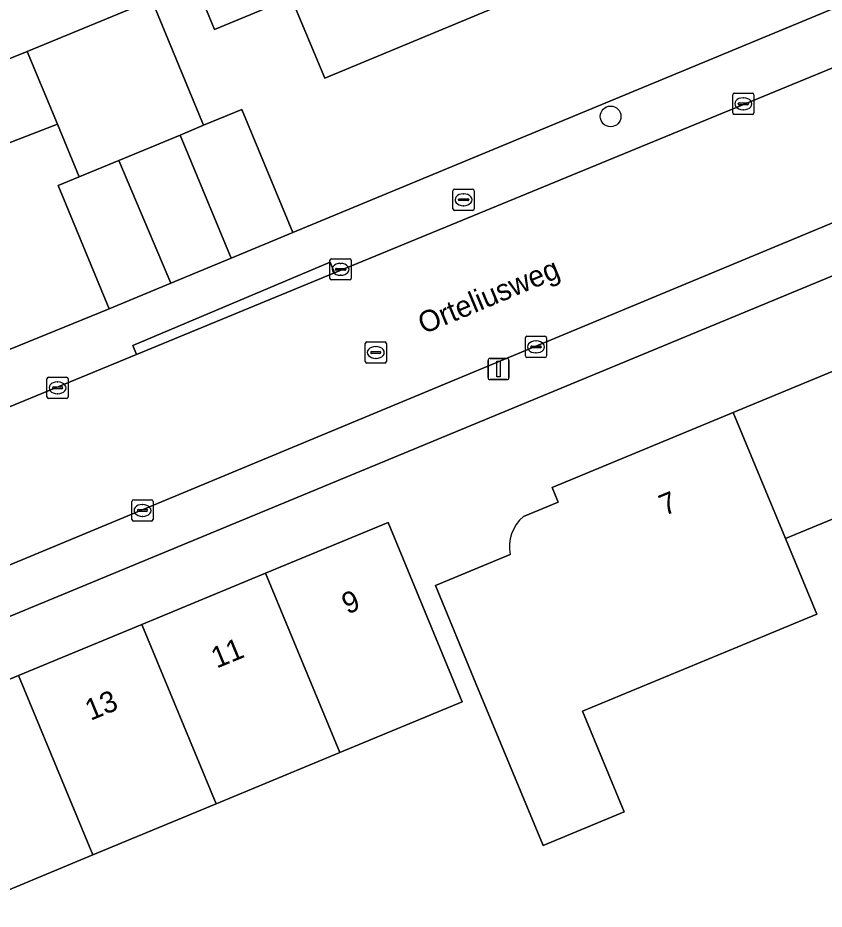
# Model space of a CAD drawing. Extents: x 162989 to 165008, y 383432 to 384338.
# Drawn here: x 163906.47 to 163944.51, y 383891.46 to 383933.52 of the extents above; entities that cross this region are included whole.
import ezdxf

# ---------------------------------------------------------------- set-up
doc = ezdxf.new("R2010")
doc.units = 0
for name, color, linetype in [('IMGEO_Boom', 7, 'Continuous'), ('IMGEO_Brandkraan', 7, 'Continuous'), ('IMGEO_Erf', 7, 'Continuous'), ('IMGEO_Kolk', 7, 'Continuous'), ('IMGEO_Lichtmast', 7, 'Continuous'), ('IMGEO_Openbare_ruimte_label', 7, 'Continuous'), ('IMGEO_Pand', 7, 'Continuous'), ('IMGEO_Pand_nummerreeks', 7, 'Continuous'), ('IMGEO_Rijbaan_lokaal_open', 7, 'Continuous'), ('IMGEO_Rioolput', 7, 'Continuous'), ('IMGEO_Voetpad_open', 7, 'Continuous')]:
    doc.layers.add(name, color=color, linetype=linetype)

msp = doc.modelspace()

# ---------------------------------------------------------------- linework, layer by layer
at = {"layer": 'IMGEO_Boom'}
msp.add_circle((163934.436, 383928.867), 0.489, dxfattribs=at)
at = {"layer": 'IMGEO_Brandkraan'}
for p, q in [((163926.998, 383924.509), (163926.998, 383925.361)), ((163927.073, 383925.435), (163927.925, 383925.435)), ((163927.999, 383925.361), (163927.999, 383924.509)), ((163927.257, 383924.929), (163927.257, 383924.941)), ((163927.695, 383924.892), (163927.297, 383924.892)), ((163927.3, 383924.978), (163927.698, 383924.978)), ((163927.486, 383925.215), (163927.511, 383925.215)), ((163927.741, 383924.941), (163927.741, 383924.929)), ((163927.925, 383924.435), (163927.073, 383924.435)), ((163927.509, 383924.655), (163927.484, 383924.655))]:
    msp.add_line(p, q, dxfattribs=at)
for points in [[(163926.998, 383924.509), (163926.998, 383925.361)], [(163927.073, 383925.435), (163927.925, 383925.435)], [(163927.999, 383925.361), (163927.999, 383924.509)], [(163927.925, 383924.435), (163927.073, 383924.435)]]:
    msp.add_lwpolyline(points, dxfattribs=at)
for centre, radius, start, end in [((163927.075, 383925.359), 0.0765, 91.552, 178.448), ((163927.075, 383925.359), 0.0765, 91.552, 178.448), ((163927.923, 383925.359), 0.0765, 1.552, 88.448), ((163927.923, 383925.359), 0.0765, 1.552, 88.448), ((163927.297, 383924.938), 0.0403, 85.8775, 175.7526), ((163927.294, 383924.928), 0.0366, 178.938, 274.7102), ((163927.698, 383924.935), 0.043, 264.8664, 352.4533), ((163927.702, 383924.94), 0.0386, 1.7309, 96.639), ((163927.075, 383924.511), 0.0765, 181.552, 268.448), ((163927.075, 383924.511), 0.0765, 181.552, 268.448), ((163927.923, 383924.511), 0.0765, 271.552, 358.448), ((163927.923, 383924.511), 0.0765, 271.552, 358.448)]:
    msp.add_arc(centre, radius, start, end, dxfattribs=at)
for centre, major_axis, ratio, start_param, end_param in [((163927.485, 383924.935), (-0.387, 0.002), 0.722429, 4.712389, 7.853982), ((163927.51, 383924.935), (-0.39, 0.002), 0.717154, 1.570796, 4.712389)]:
    msp.add_ellipse(centre, major_axis=major_axis, ratio=ratio, start_param=start_param, end_param=end_param, dxfattribs=at)
at = {"layer": 'IMGEO_Erf'}
for points in [[(163946.821, 383941.418), (163938.242, 383937.855), (163929.662, 383934.293), (163920.948, 383930.674), (163919.371, 383934.472), (163915.75, 383932.969), (163914.83, 383935.186), (163918.45, 383936.689), (163927.165, 383940.307), (163929.854, 383941.424), (163928.821, 383943.984), (163931.569, 383945.125), (163931.805, 383944.556), (163934.921, 383945.85), (163934.549, 383946.958), (163943.055, 383950.486), (163944.361, 383947.342), (163949.293, 383949.389)], [(163903.673, 383930.627), (163906.917, 383931.923), (163912.786, 383934.359), (163915.238, 383928.452), (163917.039, 383929.2), (163919.451, 383923.393), (163973.469, 383945.794)], [(163964.512, 383929.456), (163893.635, 383900.12), (163894.721, 383897.605), (163900.679, 383900.072), (163906.5, 383902.482), (163912.322, 383904.893), (163918.161, 383907.311), (163923.936, 383909.702), (163927.44, 383901.238), (163921.666, 383898.847), (163915.826, 383896.429), (163910.005, 383894.018), (163904.184, 383891.608), (163898.226, 383889.141)], [(163900.656, 383915.672), (163910.782, 383919.794), (163908.371, 383925.6), (163909.37, 383926.015), (163908.336, 383928.506), (163904.998, 383927.211)], [(163930.32, 383909.987), (163931.964, 383910.668), (163931.677, 383911.36), (163940.224, 383914.899), (163948.809, 383918.454)], [(163948.089, 383911.18), (163942.69, 383908.945), (163944.168, 383905.374), (163941.778, 383904.385), (163933.11, 383900.797), (163935.075, 383896.047), (163931.249, 383894.463), (163928.082, 383902.114), (163926.17, 383906.733), (163929.7, 383908.194)]]:
    msp.add_lwpolyline(points, dxfattribs=at)
msp.add_arc((163931.55, 383908.558), 1.885, 130.7192, 191.1311, dxfattribs=at)
at = {"layer": 'IMGEO_Kolk'}
for p, q in [((163940.198, 383929.037), (163940.198, 383929.889)), ((163940.273, 383929.963), (163941.125, 383929.963)), ((163941.199, 383929.889), (163941.199, 383929.037)), ((163940.457, 383929.457), (163940.457, 383929.469)), ((163940.5, 383929.506), (163940.898, 383929.506)), ((163940.686, 383929.743), (163940.711, 383929.743)), ((163940.941, 383929.469), (163940.941, 383929.457)), ((163940.895, 383929.42), (163940.497, 383929.42)), ((163940.709, 383929.183), (163940.684, 383929.183)), ((163941.125, 383928.963), (163940.273, 383928.963)), ((163921.196, 383921.225), (163921.196, 383922.077)), ((163921.271, 383922.151), (163922.123, 383922.151)), ((163921.684, 383921.931), (163921.709, 383921.931)), ((163922.197, 383922.077), (163922.197, 383921.225)), ((163921.455, 383921.645), (163921.455, 383921.657)), ((163921.893, 383921.608), (163921.495, 383921.608)), ((163921.498, 383921.694), (163921.896, 383921.694)), ((163921.939, 383921.657), (163921.939, 383921.645)), ((163922.123, 383921.151), (163921.271, 383921.151)), ((163921.707, 383921.371), (163921.682, 383921.371)), ((163930.414, 383917.564), (163930.414, 383918.416)), ((163930.489, 383918.49), (163931.341, 383918.49)), ((163930.902, 383918.27), (163930.927, 383918.27)), ((163931.415, 383918.416), (163931.415, 383917.564)), ((163930.673, 383917.984), (163930.673, 383917.996)), ((163931.111, 383917.947), (163930.713, 383917.947)), ((163930.716, 383918.033), (163931.114, 383918.033)), ((163930.925, 383917.71), (163930.9, 383917.71)), ((163931.157, 383917.996), (163931.157, 383917.984)), ((163931.341, 383917.49), (163930.489, 383917.49)), ((163907.846, 383915.633), (163907.846, 383916.485)), ((163907.921, 383916.559), (163908.773, 383916.559)), ((163908.847, 383916.485), (163908.847, 383915.633)), ((163908.105, 383916.053), (163908.105, 383916.065)), ((163908.543, 383916.016), (163908.145, 383916.016)), ((163908.148, 383916.102), (163908.546, 383916.102)), ((163908.334, 383916.339), (163908.359, 383916.339)), ((163908.589, 383916.065), (163908.589, 383916.053)), ((163908.357, 383915.779), (163908.332, 383915.779)), ((163908.773, 383915.559), (163907.921, 383915.559)), ((163911.852, 383909.847), (163911.852, 383910.699)), ((163911.927, 383910.773), (163912.779, 383910.773)), ((163912.34, 383910.553), (163912.365, 383910.553)), ((163912.853, 383910.699), (163912.853, 383909.847)), ((163912.111, 383910.267), (163912.111, 383910.279)), ((163912.549, 383910.23), (163912.151, 383910.23)), ((163912.154, 383910.316), (163912.552, 383910.316)), ((163912.595, 383910.279), (163912.595, 383910.267)), ((163912.779, 383909.773), (163911.927, 383909.773)), ((163912.363, 383909.993), (163912.338, 383909.993))]:
    msp.add_line(p, q, dxfattribs=at)
for points in [[(163940.198, 383929.037), (163940.198, 383929.889)], [(163940.273, 383929.963), (163941.125, 383929.963)], [(163941.199, 383929.889), (163941.199, 383929.037)], [(163941.125, 383928.963), (163940.273, 383928.963)], [(163921.196, 383921.225), (163921.196, 383922.077)], [(163921.271, 383922.151), (163922.123, 383922.151)], [(163922.197, 383922.077), (163922.197, 383921.225)], [(163922.123, 383921.151), (163921.271, 383921.151)], [(163930.414, 383917.564), (163930.414, 383918.416)], [(163930.489, 383918.49), (163931.341, 383918.49)], [(163931.415, 383918.416), (163931.415, 383917.564)], [(163931.341, 383917.49), (163930.489, 383917.49)], [(163907.846, 383915.633), (163907.846, 383916.485)], [(163907.921, 383916.559), (163908.773, 383916.559)], [(163908.847, 383916.485), (163908.847, 383915.633)], [(163908.773, 383915.559), (163907.921, 383915.559)], [(163911.852, 383909.847), (163911.852, 383910.699)], [(163911.927, 383910.773), (163912.779, 383910.773)], [(163912.853, 383910.699), (163912.853, 383909.847)], [(163912.779, 383909.773), (163911.927, 383909.773)]]:
    msp.add_lwpolyline(points, dxfattribs=at)
for centre, radius, start, end in [((163940.275, 383929.887), 0.0765, 91.552, 178.448), ((163940.275, 383929.887), 0.0765, 91.552, 178.448), ((163941.123, 383929.887), 0.0765, 1.552, 88.448), ((163941.123, 383929.887), 0.0765, 1.552, 88.448), ((163940.497, 383929.466), 0.0403, 85.8775, 175.7526), ((163940.494, 383929.456), 0.0366, 178.938, 274.7102), ((163940.898, 383929.463), 0.043, 264.8664, 352.4533), ((163940.902, 383929.468), 0.0386, 1.7309, 96.639), ((163940.275, 383929.039), 0.0765, 181.552, 268.448), ((163940.275, 383929.039), 0.0765, 181.552, 268.448), ((163941.123, 383929.039), 0.0765, 271.552, 358.448), ((163941.123, 383929.039), 0.0765, 271.552, 358.448), ((163921.273, 383922.075), 0.0765, 91.552, 178.448), ((163921.273, 383922.075), 0.0765, 91.552, 178.448), ((163922.121, 383922.075), 0.0765, 1.552, 88.448), ((163922.121, 383922.075), 0.0765, 1.552, 88.448), ((163921.495, 383921.654), 0.0403, 85.8775, 175.7526), ((163921.492, 383921.644), 0.0366, 178.938, 274.7102), ((163921.896, 383921.651), 0.043, 264.8664, 352.4533), ((163921.9, 383921.656), 0.0386, 1.7309, 96.639), ((163921.273, 383921.227), 0.0765, 181.552, 268.448), ((163921.273, 383921.227), 0.0765, 181.552, 268.448), ((163922.121, 383921.227), 0.0765, 271.552, 358.448), ((163922.121, 383921.227), 0.0765, 271.552, 358.448), ((163930.491, 383918.414), 0.0765, 91.552, 178.448), ((163930.491, 383918.414), 0.0765, 91.552, 178.448), ((163931.339, 383918.414), 0.0765, 1.552, 88.448), ((163931.339, 383918.414), 0.0765, 1.552, 88.448), ((163930.713, 383917.993), 0.0403, 85.8775, 175.7526), ((163930.71, 383917.983), 0.0366, 178.938, 274.7102), ((163931.114, 383917.99), 0.043, 264.8664, 352.4533), ((163931.118, 383917.995), 0.0386, 1.7309, 96.639), ((163930.491, 383917.566), 0.0765, 181.552, 268.448), ((163930.491, 383917.566), 0.0765, 181.552, 268.448), ((163931.339, 383917.566), 0.0765, 271.552, 358.448), ((163931.339, 383917.566), 0.0765, 271.552, 358.448), ((163907.923, 383916.483), 0.0765, 91.552, 178.448), ((163907.923, 383916.483), 0.0765, 91.552, 178.448), ((163908.771, 383916.483), 0.0765, 1.552, 88.448), ((163908.771, 383916.483), 0.0765, 1.552, 88.448), ((163908.145, 383916.062), 0.0403, 85.8775, 175.7526), ((163908.142, 383916.052), 0.0366, 178.938, 274.7102), ((163908.546, 383916.059), 0.043, 264.8664, 352.4533), ((163908.55, 383916.064), 0.0386, 1.7309, 96.639), ((163907.923, 383915.635), 0.0765, 181.552, 268.448), ((163907.923, 383915.635), 0.0765, 181.552, 268.448), ((163908.771, 383915.635), 0.0765, 271.552, 358.448), ((163908.771, 383915.635), 0.0765, 271.552, 358.448), ((163911.929, 383910.697), 0.0765, 91.552, 178.448), ((163911.929, 383910.697), 0.0765, 91.552, 178.448), ((163912.777, 383910.697), 0.0765, 1.552, 88.448), ((163912.777, 383910.697), 0.0765, 1.552, 88.448), ((163912.151, 383910.276), 0.0403, 85.8775, 175.7526), ((163912.148, 383910.266), 0.0366, 178.938, 274.7102), ((163912.552, 383910.273), 0.043, 264.8664, 352.4533), ((163912.556, 383910.278), 0.0386, 1.7309, 96.639), ((163911.929, 383909.849), 0.0765, 181.552, 268.448), ((163911.929, 383909.849), 0.0765, 181.552, 268.448), ((163912.777, 383909.849), 0.0765, 271.552, 358.448), ((163912.777, 383909.849), 0.0765, 271.552, 358.448)]:
    msp.add_arc(centre, radius, start, end, dxfattribs=at)
for centre, major_axis, ratio, start_param, end_param in [((163940.685, 383929.463), (-0.387, 0.002), 0.722429, 4.712389, 7.853982), ((163940.71, 383929.463), (-0.39, 0.002), 0.717154, 1.570796, 4.712389), ((163921.683, 383921.651), (-0.387, 0.002), 0.722429, 4.712389, 7.853982), ((163921.708, 383921.651), (-0.39, 0.002), 0.717154, 1.570796, 4.712389), ((163930.901, 383917.99), (-0.387, 0.002), 0.722429, 4.712389, 7.853982), ((163930.926, 383917.99), (-0.39, 0.002), 0.717154, 1.570796, 4.712389), ((163908.333, 383916.059), (-0.387, 0.002), 0.722429, 4.712389, 7.853982), ((163908.358, 383916.059), (-0.39, 0.002), 0.717154, 1.570796, 4.712389), ((163912.339, 383910.273), (-0.387, 0.002), 0.722429, 4.712389, 7.853982), ((163912.364, 383910.273), (-0.39, 0.002), 0.717154, 1.570796, 4.712389)]:
    msp.add_ellipse(centre, major_axis=major_axis, ratio=ratio, start_param=start_param, end_param=end_param, dxfattribs=at)
at = {"layer": 'IMGEO_Lichtmast'}
for p, q in [((163928.653, 383916.546), (163928.653, 383917.346)), ((163928.653, 383917.346), (163928.653, 383916.546)), ((163928.753, 383917.446), (163929.543, 383917.446)), ((163929.543, 383917.446), (163928.753, 383917.446)), ((163929.643, 383917.346), (163929.643, 383916.546)), ((163929.643, 383916.546), (163929.643, 383917.346)), ((163929.543, 383916.446), (163928.753, 383916.446)), ((163928.753, 383916.446), (163929.543, 383916.446))]:
    msp.add_line(p, q, dxfattribs=at)
msp.add_lwpolyline([(163929.073, 383917.321), (163929.223, 383917.321), (163929.223, 383916.571), (163929.073, 383916.571), (163929.073, 383917.321)], dxfattribs=at)
for centre, start, end in [((163928.753, 383917.346), 90, 180), ((163928.753, 383917.346), 90, 180), ((163929.543, 383917.346), 0, 90), ((163929.543, 383917.346), 360, 90), ((163928.753, 383916.546), 180, 270), ((163928.753, 383916.546), 180, 270), ((163929.543, 383916.546), 270, 0), ((163929.543, 383916.546), 270, 0)]:
    msp.add_arc(centre, 0.1, start, end, dxfattribs=at)
at = {"layer": 'IMGEO_Pand'}
for points in [[(163927.165, 383940.307), (163918.45, 383936.689), (163914.83, 383935.186), (163915.75, 383932.969), (163919.371, 383934.472), (163920.948, 383930.674), (163929.662, 383934.293)], [(163906.917, 383931.923), (163908.336, 383928.506), (163909.37, 383926.015), (163911.233, 383926.789), (163914.124, 383927.989), (163915.238, 383928.452), (163912.786, 383934.359)], [(163906.917, 383931.923), (163903.673, 383930.627), (163904.998, 383927.211), (163908.336, 383928.506)], [(163917.039, 383929.2), (163915.238, 383928.452), (163914.124, 383927.989), (163916.535, 383922.182), (163919.451, 383923.393)], [(163913.691, 383921.002), (163916.535, 383922.182), (163914.124, 383927.989), (163911.233, 383926.789)], [(163911.233, 383926.789), (163909.37, 383926.015), (163908.371, 383925.6), (163910.782, 383919.794), (163913.691, 383921.002)], [(163948.809, 383918.454), (163940.224, 383914.899), (163942.69, 383908.945), (163948.089, 383911.18), (163949.202, 383908.493), (163952.378, 383909.835), (163951.274, 383912.499)], [(163918.161, 383907.311), (163921.666, 383898.847), (163927.44, 383901.238), (163923.936, 383909.702)], [(163915.826, 383896.429), (163921.666, 383898.847), (163918.161, 383907.311), (163912.322, 383904.893)], [(163915.826, 383896.429), (163912.322, 383904.893), (163906.5, 383902.482), (163910.005, 383894.018)], [(163906.5, 383902.482), (163900.679, 383900.072), (163904.184, 383891.608), (163910.005, 383894.018)]]:
    msp.add_lwpolyline(points, close=True, dxfattribs=at)
msp.add_lwpolyline([(163929.7, 383908.194), (163926.17, 383906.733), (163928.082, 383902.114), (163931.249, 383894.463), (163935.075, 383896.047), (163933.11, 383900.797), (163941.778, 383904.385), (163944.168, 383905.374), (163942.69, 383908.945), (163940.224, 383914.899), (163931.677, 383911.36), (163931.964, 383910.668), (163930.32, 383909.987)], dxfattribs=at)
msp.add_arc((163931.55, 383908.558), 1.885, 130.7192, 191.1311, dxfattribs=at)
at = {"layer": 'IMGEO_Rijbaan_lokaal_open'}
msp.add_lwpolyline([(163978.45, 383944.988), (163974.838, 383943.5), (163971.509, 383942.128), (163921.411, 383921.486), (163912.068, 383917.637), (163890.075, 383908.575), (163892.626, 383902.3), (163892.691, 383902.14), (163982.692, 383939.577)], dxfattribs=at)
at = {"layer": 'IMGEO_Rioolput'}
for p, q in [((163922.859, 383917.301), (163922.859, 383918.153)), ((163922.934, 383918.227), (163923.786, 383918.227)), ((163923.86, 383918.153), (163923.86, 383917.301)), ((163923.118, 383917.721), (163923.118, 383917.733)), ((163923.556, 383917.684), (163923.158, 383917.684)), ((163923.161, 383917.77), (163923.559, 383917.77)), ((163923.347, 383918.007), (163923.372, 383918.007)), ((163923.602, 383917.733), (163923.602, 383917.721)), ((163923.37, 383917.447), (163923.345, 383917.447)), ((163923.786, 383917.227), (163922.934, 383917.227))]:
    msp.add_line(p, q, dxfattribs=at)
for points in [[(163922.859, 383917.301), (163922.859, 383918.153)], [(163922.934, 383918.227), (163923.786, 383918.227)], [(163923.86, 383918.153), (163923.86, 383917.301)], [(163923.786, 383917.227), (163922.934, 383917.227)]]:
    msp.add_lwpolyline(points, dxfattribs=at)
for centre, radius, start, end in [((163922.936, 383918.151), 0.0765, 91.552, 178.448), ((163922.936, 383918.151), 0.0765, 91.552, 178.448), ((163923.784, 383918.151), 0.0765, 1.552, 88.448), ((163923.784, 383918.151), 0.0765, 1.552, 88.448), ((163923.158, 383917.73), 0.0403, 85.8775, 175.7526), ((163923.155, 383917.72), 0.0366, 178.938, 274.7102), ((163923.559, 383917.727), 0.043, 264.8664, 352.4533), ((163923.563, 383917.732), 0.0386, 1.7309, 96.639), ((163922.936, 383917.303), 0.0765, 181.552, 268.448), ((163922.936, 383917.303), 0.0765, 181.552, 268.448), ((163923.784, 383917.303), 0.0765, 271.552, 358.448), ((163923.784, 383917.303), 0.0765, 271.552, 358.448)]:
    msp.add_arc(centre, radius, start, end, dxfattribs=at)
for centre, major_axis, ratio, start_param, end_param in [((163923.346, 383917.727), (-0.387, 0.002), 0.722429, 4.712389, 7.853982), ((163923.371, 383917.727), (-0.39, 0.002), 0.717154, 1.570796, 4.712389)]:
    msp.add_ellipse(centre, major_axis=major_axis, ratio=ratio, start_param=start_param, end_param=end_param, dxfattribs=at)
at = {"layer": 'IMGEO_Voetpad_open'}
for points in [[(163971.509, 383942.128), (163971.319, 383942.59), (163974.369, 383943.847), (163974.648, 383943.962), (163973.469, 383945.794), (163919.451, 383923.393), (163916.535, 383922.182), (163913.691, 383921.002), (163910.782, 383919.794), (163900.656, 383915.672), (163892.311, 383912.344), (163889.038, 383911.071), (163890.075, 383908.575), (163912.068, 383917.637), (163911.892, 383918.062), (163921.205, 383921.984), (163921.411, 383921.486)], [(163964.512, 383929.456), (163965.841, 383930.006), (163982.902, 383937.067), (163985.056, 383936.458), (163982.692, 383939.577), (163892.691, 383902.14), (163893.635, 383900.12)], [(163921.411, 383921.486), (163921.205, 383921.984), (163911.892, 383918.062), (163912.068, 383917.637)]]:
    msp.add_lwpolyline(points, close=True, dxfattribs=at)

# ---------------------------------------------------------------- texts
at = {"layer": 'IMGEO_Openbare_ruimte_label'}
msp.add_text('Orteliusweg', height=1, rotation=22.6419, dxfattribs=at).set_placement((163925.612, 383918.581))
at = {"layer": 'IMGEO_Pand_nummerreeks'}
for s, rotation, p in [('7', 22.4925, (163936.981, 383910.005)), ('9', 22.4929, (163922.015, 383905.356)), ('11', 22.4929, (163915.852, 383902.806)), ('13', 22.4929, (163909.904, 383900.342))]:
    msp.add_text(s, height=1, rotation=rotation, dxfattribs=at).set_placement(p)

doc.saveas('drawing.dxf')
